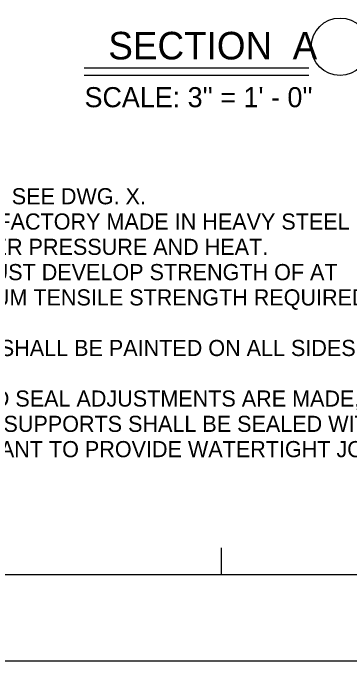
# Model space of a CAD drawing. Extents: x 22371.58 to 22374.41, y 22370.57 to 22372.4.
# Drawn here: x 22372.1082 to 22372.3521, y 22370.5694 to 22371.0393 of the extents above; entities that cross this region are included whole.
import ezdxf

# ---------------------------------------------------------------- set-up
doc = ezdxf.new("R2010")
doc.units = 0
for name, color, linetype in [('G-ANNO-SYMB', 7, 'Continuous'), ('G-ANNO-TTBL', 7, 'Continuous'), ('S-ANNO-NOTE', 7, 'Continuous'), ('S-ANNO-TEXT', 7, 'Continuous'), ('S-GATE-SEAL', 7, 'Continuous')]:
    doc.layers.add(name, color=color, linetype=linetype)

msp = doc.modelspace()

# ---------------------------------------------------------------- linework, layer by layer
at = {"layer": 'G-ANNO-SYMB'}
msp.add_lwpolyline([(22371.57831, 22372.40278), (22374.41164, 22372.40278), (22374.41164, 22370.56945), (22371.57831, 22370.56945)], close=True, dxfattribs=at)
at = {"layer": 'G-ANNO-TTBL'}
msp.add_line((22372.25962, 22370.63195), (22372.25962, 22370.65163), dxfattribs=at)
msp.add_lwpolyline([(22371.77622, 22372.34028), (22374.19289, 22372.34028), (22374.19289, 22370.63195), (22371.77622, 22370.63195)], close=True, dxfattribs=at)
msp.add_lwpolyline([(22371.77622, 22372.34028), (22374.19289, 22372.34028), (22374.19289, 22370.63195), (22371.77622, 22370.63195)], close=True, dxfattribs=at)
at = {"layer": 'S-ANNO-TEXT'}
for p, q in [((22372.15981, 22370.99945), (22372.32292, 22370.99945)), ((22372.15981, 22370.99424), (22372.32292, 22370.99424))]:
    msp.add_line(p, q, dxfattribs=at)
msp.add_circle((22372.34553, 22371.01474), 0.02083, dxfattribs=at)

# ---------------------------------------------------------------- texts
at = {"layer": 'S-ANNO-NOTE'}
for s, p in [('FOR GENERAL NOTES, SEE DWG. X.', (22371.9283, 22370.90056)), ('ALL SPLICES WILL BE FACTORY MADE IN HEAVY STEEL', (22371.9283, 22370.88223)), ('PRESS TYPE MOLDS UNDER PRESSURE AND HEAT.', (22371.89705, 22370.86389)), ('ALL SPLICE JOINTS MUST DEVELOP STRENGTH OF AT', (22371.9283, 22370.84556)), ('LEAST 50% OF THE MINIMUM TENSILE STRENGTH REQUIRED', (22371.89705, 22370.82723)), ('SEAL CLAMP ANGLES SHALL BE PAINTED ON ALL SIDES', (22371.9283, 22370.79056)), ('AFTER ASSEMBLY AND SEAL ADJUSTMENTS ARE MADE,  ALL', (22371.9283, 22370.75389)), ('GAPS IN SEALS AND SEAL SUPPORTS SHALL BE SEALED WITH', (22371.89705, 22370.73556)), ('A SILICONE RUBBER SEALANT TO PROVIDE WATERTIGHT JOINTS.', (22371.89705, 22370.71723))]:
    msp.add_text(s, height=0.0116979, dxfattribs=at).set_placement(p)
at = {"layer": 'S-ANNO-TEXT'}
msp.add_text('SECTION  A', height=0.02, dxfattribs=at).set_placement((22372.17741, 22371.00558))
at = {"layer": 'S-GATE-SEAL'}
msp.add_text("SCALE: 3'' = 1' - 0''", height=0.0145831, dxfattribs=at).set_placement((22372.16018, 22370.97093))

doc.saveas('drawing.dxf')
